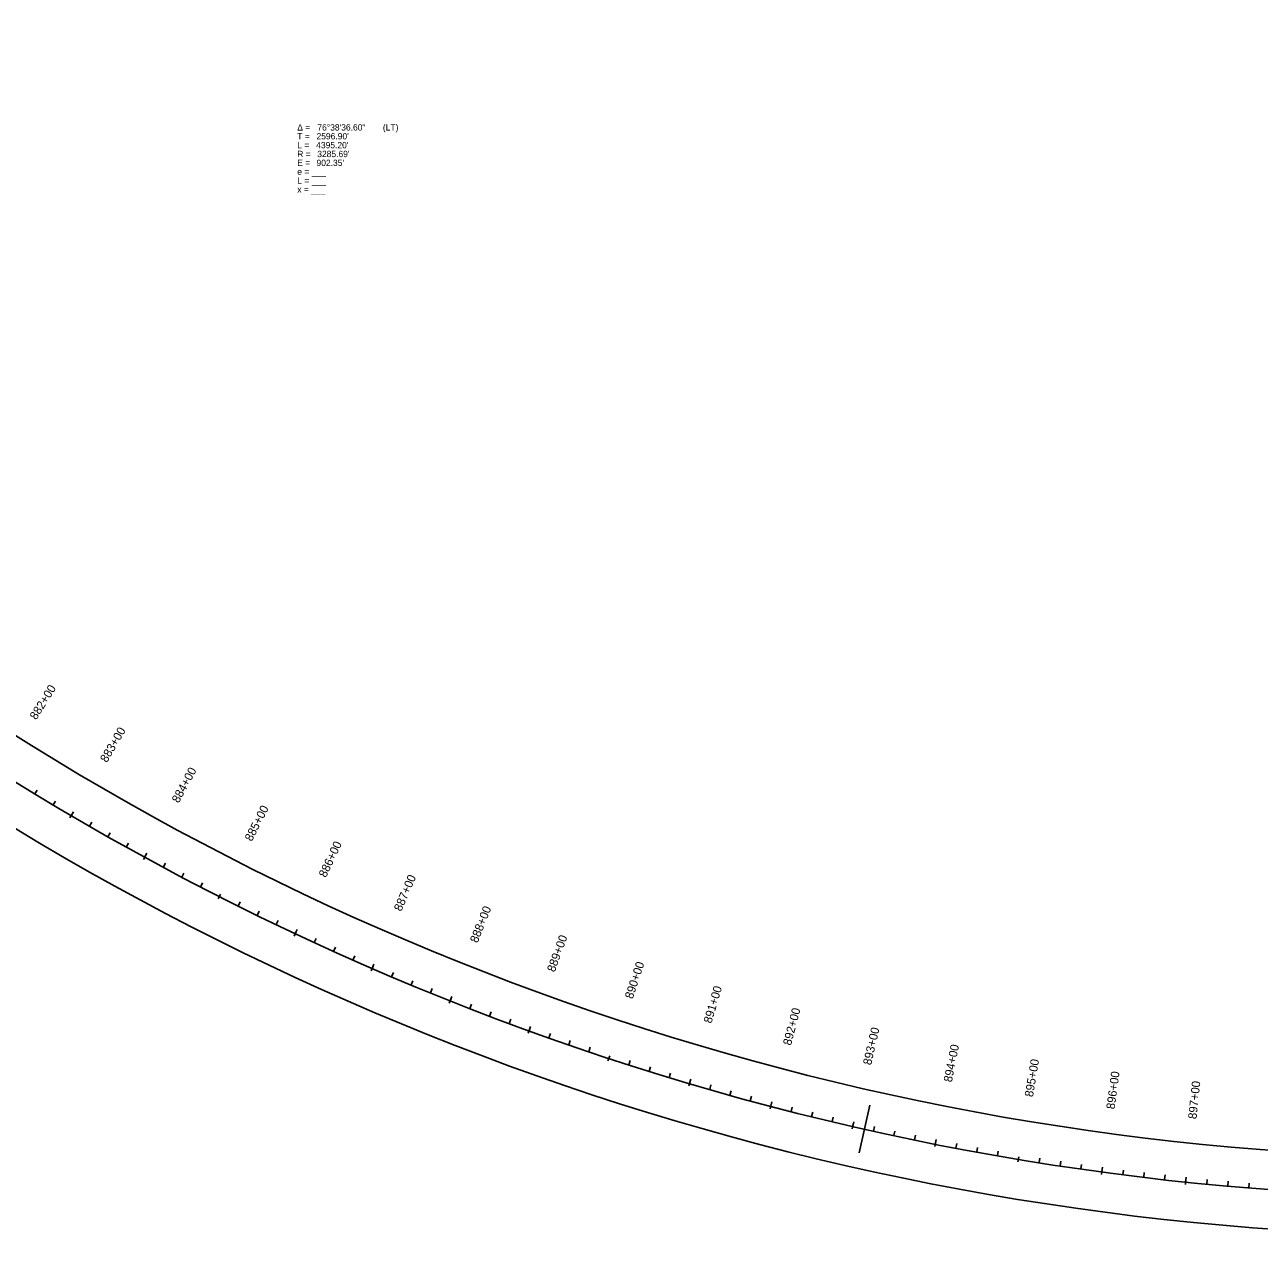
# Model space of a CAD drawing. Extents: x 14448949 to 14455476, y 8570587 to 8573998.
# Drawn here: x 14450748 to 14452210, y 8570851 to 8572286 of the extents above; entities that cross this region are included whole.
import ezdxf

# ---------------------------------------------------------------- set-up
doc = ezdxf.new("R2010")
doc.units = 0
for name, color, linetype in [('Alignment', 7, 'Continuous'), ('TextAlignment', 7, 'Continuous'), ('TextAlignmentLrg', 7, 'Continuous'), ('TextAlignmentSml', 7, 'Continuous'), ('TextNonPlot', 7, 'Continuous')]:
    doc.layers.add(name, color=color, linetype=linetype)

msp = doc.modelspace()

# ---------------------------------------------------------------- linework, layer by layer
at = {"layer": 'Alignment'}
msp.add_arc((14452465.5, 8574183.5), 3285.7, 198.0445, 274.688, dxfattribs=at)
msp.add_arc((14452465.5, 8574183.5), 3285.7, 198.0445, 274.688, dxfattribs=at)
at = {"layer": 'TextAlignmentLrg'}
for p, q in [((14450803.1, 8571349.4), (14450805.8, 8571354.1)), ((14450890.1, 8571300.2), (14450892.7, 8571304.9)), ((14450979.9, 8571256.3), (14450977.2, 8571250.8)), ((14451068.4, 8571209.7), (14451070.7, 8571214.6)), ((14451159.6, 8571168.5), (14451161.7, 8571173.5)), ((14451251.9, 8571130.2), (14451253.9, 8571135.3)), ((14451345.4, 8571094.7), (14451347.2, 8571099.8)), ((14451440.9, 8571064.9), (14451438.9, 8571059.1)), ((14451535.4, 8571032.3), (14451536.9, 8571037.5)), ((14451631.7, 8571005.4), (14451633.1, 8571010.7)), ((14451728.8, 8570981.5), (14451730, 8570986.8)), ((14451826.6, 8570960.6), (14451827.6, 8570965.9)), ((14451925.4, 8570945.6), (14451924.4, 8570939.6)), ((14452023.8, 8570927.7), (14452024.5, 8570933.1)), ((14452123.1, 8570915.7), (14452123.7, 8570921.2))]:
    msp.add_line(p, q, dxfattribs=at)
at = {"layer": 'TextAlignmentSml'}
for p, q in [((14450760.1, 8571375.1), (14450763, 8571379.7)), ((14450781.6, 8571362.2), (14450784.4, 8571366.8)), ((14450804.6, 8571352.1), (14450801.5, 8571346.8)), ((14450824.7, 8571336.9), (14450827.4, 8571341.6)), ((14450846.4, 8571324.5), (14450849.1, 8571329.2)), ((14450868.2, 8571312.2), (14450870.9, 8571317)), ((14450891.6, 8571302.8), (14450888.6, 8571297.5)), ((14450912.1, 8571288.2), (14450914.7, 8571293.1)), ((14450934.2, 8571276.5), (14450936.7, 8571281.3)), ((14450956.3, 8571264.9), (14450958.8, 8571269.8)), ((14450979.9, 8571256.3), (14450977.2, 8571250.8)), ((14451000.9, 8571242.3), (14451003.3, 8571247.2)), ((14451023.3, 8571231.3), (14451025.7, 8571236.2)), ((14451045.8, 8571220.4), (14451048.2, 8571225.3)), ((14451069.7, 8571212.4), (14451067.1, 8571206.9)), ((14451091.1, 8571199.1), (14451093.4, 8571204.1)), ((14451113.8, 8571188.7), (14451116.1, 8571193.7)), ((14451136.7, 8571178.5), (14451138.9, 8571183.5)), ((14451160.8, 8571171.3), (14451158.3, 8571165.7)), ((14451182.5, 8571158.7), (14451184.7, 8571163.7)), ((14451205.6, 8571149), (14451207.7, 8571154)), ((14451228.7, 8571139.5), (14451230.8, 8571144.6)), ((14451253, 8571133), (14451250.8, 8571127.3)), ((14451275.2, 8571121), (14451277.2, 8571126.1)), ((14451298.5, 8571112.1), (14451300.5, 8571117.2)), ((14451321.9, 8571103.3), (14451323.8, 8571108.4)), ((14451346.4, 8571097.5), (14451344.3, 8571091.8)), ((14451368.9, 8571086.2), (14451370.7, 8571091.4)), ((14451392.5, 8571078), (14451394.3, 8571083.1)), ((14451416.2, 8571069.9), (14451417.9, 8571075.1)), ((14451440.9, 8571064.9), (14451438.9, 8571059.1)), ((14451463.7, 8571054.3), (14451465.3, 8571059.5)), ((14451487.5, 8571046.8), (14451489.1, 8571052)), ((14451511.4, 8571039.4), (14451513, 8571044.6)), ((14451536.2, 8571035.2), (14451534.5, 8571029.3)), ((14451559.4, 8571025.3), (14451560.9, 8571030.5)), ((14451583.4, 8571018.5), (14451584.9, 8571023.7)), ((14451607.5, 8571011.8), (14451609, 8571017.1)), ((14451632.5, 8571008.4), (14451630.9, 8571002.4)), ((14451655.9, 8570999.2), (14451657.2, 8571004.4)), ((14451680.1, 8570993.1), (14451681.5, 8570998.4)), ((14451704.4, 8570987.2), (14451705.7, 8570992.5)), ((14451729.5, 8570984.5), (14451728.1, 8570978.5)), ((14451753.2, 8570976), (14451754.4, 8570981.3)), ((14451777.6, 8570970.7), (14451778.7, 8570976)), ((14451802.1, 8570965.5), (14451803.2, 8570970.9)), ((14451827.2, 8570963.6), (14451826, 8570957.6)), ((14451851.1, 8570955.8), (14451852.1, 8570961.2)), ((14451875.7, 8570951.2), (14451876.7, 8570956.6)), ((14451900.3, 8570946.8), (14451901.2, 8570952.2)), ((14451925.4, 8570945.6), (14451924.4, 8570939.6)), ((14451949.6, 8570938.6), (14451950.5, 8570944)), ((14451974.3, 8570934.8), (14451975.1, 8570940.2)), ((14451999.1, 8570931.1), (14451999.8, 8570936.5)), ((14452024.2, 8570930.7), (14452023.4, 8570924.6)), ((14452048.6, 8570924.4), (14452049.3, 8570929.8)), ((14452073.4, 8570921.3), (14452074.1, 8570926.8)), ((14452098.2, 8570918.4), (14452098.9, 8570923.9)), ((14452123.4, 8570918.8), (14452122.8, 8570912.7)), ((14452148, 8570913.2), (14452148.5, 8570918.7)), ((14452172.9, 8570910.9), (14452173.3, 8570916.4)), ((14452197.8, 8570908.8), (14452198.2, 8570914.2))]:
    msp.add_line(p, q, dxfattribs=at)
at = {"layer": 'TextNonPlot'}
msp.add_line((14451748.9, 8571006.5), (14451736.3, 8570950.2), dxfattribs=at)
for centre, radius, start, end in [((14452466.6, 8574184.2), 3240, 198.0445, 274.688), ((14452464.1, 8574181.3), 3330, 198.0899, 274.6933)]:
    msp.add_arc(centre, radius, start, end, dxfattribs=at)

# ---------------------------------------------------------------- texts
at = {"layer": 'TextAlignment'}
for s, p in [('Δ = ', (14451070.9, 8572160.8)), ('76°38\'36.60"', (14451094.7, 8572160.8)), (' (LT)', (14451169.5, 8572160.8)), ('T = ', (14451070.9, 8572150.3)), ('L = ', (14451070.9, 8572139.8)), ("4395.20'", (14451093.3, 8572139.8)), ("2596.90'", (14451093.7, 8572150.3)), ('R = ', (14451070.9, 8572129.3)), ("3285.69'", (14451094.6, 8572129.3)), ('E = ', (14451070.9, 8572118.8)), ("902.35'", (14451093.7, 8572118.8)), ('e = ___ ', (14451070.9, 8572108.3)), ('L = ___', (14451070.9, 8572097.8)), ('x = ___', (14451070.9, 8572087.3))]:
    msp.add_text(s, height=7.5, dxfattribs=at).set_placement(p)
at = {"layer": 'TextAlignmentLrg'}
for s, rotation, p in [('885+00', 63.0935, (14451017, 8571318.2)), ('890+00', 71.8125, (14451468.1, 8571131.7)), ('895+00', 80.5315, (14451942.2, 8571015.8))]:
    msp.add_text(s, height=10.02, rotation=rotation, dxfattribs=at).set_placement(p)
at = {"layer": 'TextAlignmentSml'}
for s, rotation, p in [('882+00', 57.8621, (14450761.7, 8571462.2)), ('883+00', 59.6059, (14450845.3, 8571411.6)), ('884+00', 61.3497, (14450930.4, 8571363.6)), ('885+00', 63.0935, (14451017, 8571318.2)), ('886+00', 64.8373, (14451104.8, 8571275.4)), ('887+00', 66.5811, (14451194, 8571235.4)), ('888+00', 68.3249, (14451284.3, 8571198)), ('889+00', 70.0687, (14451375.7, 8571163.5)), ('890+00', 71.8125, (14451468.1, 8571131.7)), ('891+00', 73.5563, (14451561.4, 8571102.8)), ('892+00', 75.3001, (14451655.6, 8571076.7)), ('893+00', 77.0439, (14451750.5, 8571053.5)), ('894+00', 78.7877, (14451846.1, 8571033.2)), ('895+00', 80.5315, (14451942.2, 8571015.8)), ('896+00', 82.2753, (14452038.9, 8571001.3)), ('897+00', 84.0191, (14452135.9, 8570989.8))]:
    msp.add_text(s, height=10.02, rotation=rotation, dxfattribs=at).set_placement(p)

doc.saveas('drawing.dxf')
